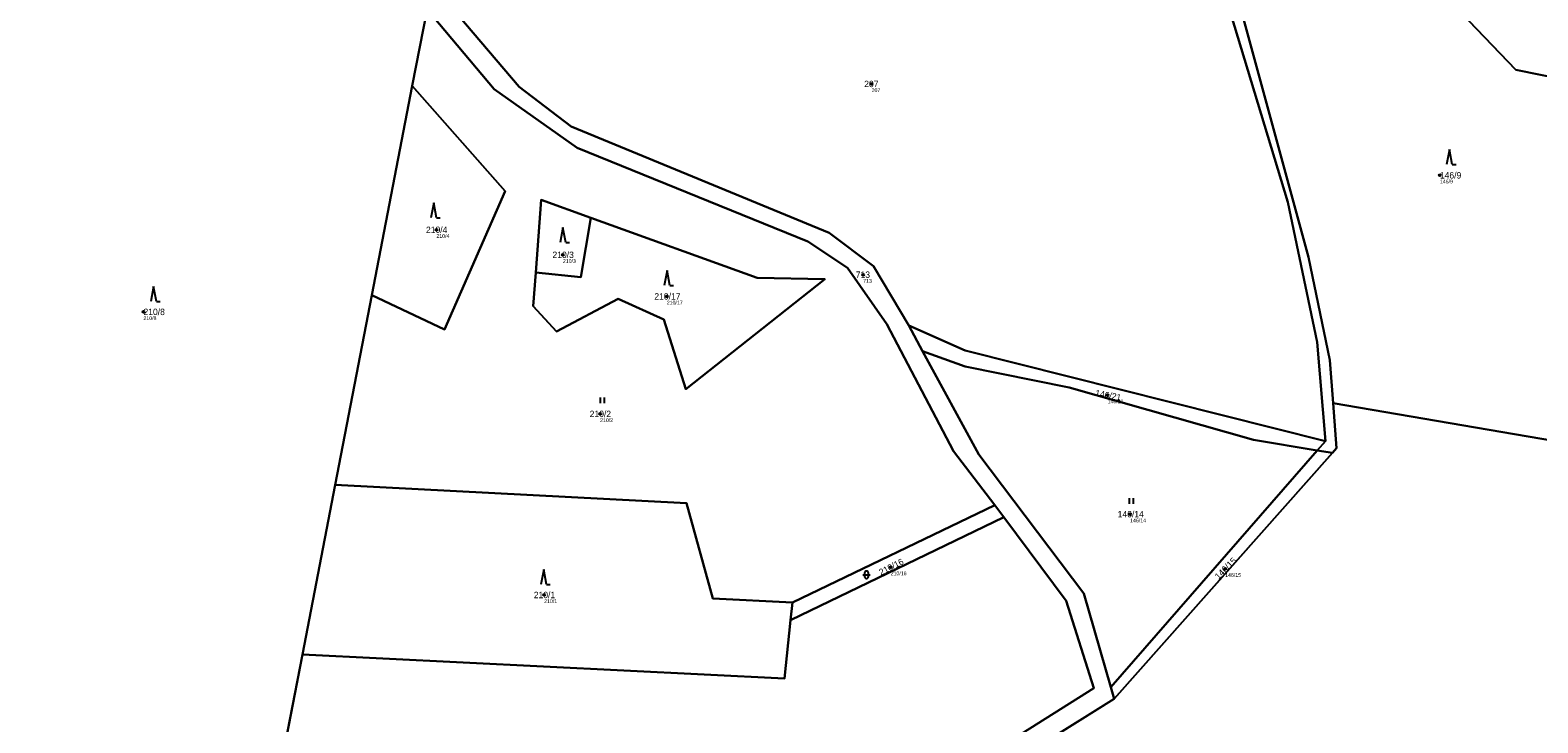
# Model space of a CAD drawing. Extents: x -767985 to -763816, y -1059600 to -1057360.
# Drawn here: x -766944 to -766543.5, y -1058891.9 to -1058707.9 of the extents above; entities that cross this region are included whole.
import ezdxf

# ---------------------------------------------------------------- set-up
doc = ezdxf.new("R2010")
doc.units = 0
for name, color, linetype in [('Definiční body', 7, 'Continuous'), ('Hranice parcel', 7, 'Continuous'), ('Parcelní čísla', 7, 'Continuous'), ('Polygon parcely', 7, 'Continuous'), ('Značky kultur', 7, 'Continuous')]:
    doc.layers.add(name, color=color, linetype=linetype)

msp = doc.modelspace()

# ---------------------------------------------------------------- linework, layer by layer
at = {"layer": 'Definiční body'}
for centre in [(-766720.51, -1058722.21994), (-766569.56, -1058746.48994), (-766836.12, -1058760.95994), (-766802.53, -1058767.60994), (-766722.75, -1058772.88994), (-766774.92, -1058778.64994), (-766913.94, -1058782.76994), (-766657.83, -1058804.88994), (-766792.64, -1058809.86994), (-766651.85, -1058836.50994), (-766715.45, -1058850.57994), (-766626.61, -1058851.01994), (-766807.49, -1058857.97994)]:
    msp.add_circle(centre, 0.25, dxfattribs=at)
at = {"layer": 'Hranice parcel'}
for p, q in [((-766838.62, -1058702.42), (-766842.53, -1058722.71)), ((-766842.53, -1058722.71), (-766853.27, -1058778.37)), ((-766853.27, -1058778.37), (-766862.98, -1058828.7)), ((-766706.99, -1058793.19), (-766710.67, -1058786.43)), ((-766597.89, -1058807.06), (-766528.98, -1058818.77)), ((-766599.95, -1058817.08), (-766602.16, -1058819.62)), ((-766656.99, -1058882.48), (-766602.16, -1058819.62)), ((-766656.1, -1058885.58), (-766598.12, -1058820.24)), ((-766598.12, -1058820.24), (-766602.16, -1058819.62)), ((-766862.98, -1058828.7), (-766871.68, -1058873.81)), ((-766741.53, -1058860.02), (-766687.74, -1058834.16)), ((-766685.37, -1058837.27), (-766687.74, -1058834.16)), ((-766685.37, -1058837.27), (-766742.02, -1058864.65)), ((-766742.02, -1058864.65), (-766741.53, -1058860.02)), ((-766880.48, -1058919.11), (-766871.68, -1058873.81)), ((-766656.99, -1058882.48), (-766656.1, -1058885.58)), ((-766711.95, -1058920.49), (-766656.1, -1058885.58))]:
    msp.add_line(p, q, dxfattribs=at)
for points in [[(-766620.1, -1058632.62), (-766622.28, -1058702.97), (-766604.44, -1058768.25), (-766598.75, -1058795.61), (-766597.89, -1058807.06)], [(-766528.98, -1058818.77), (-766521.82, -1058724.01), (-766549.35, -1058718.51), (-766561.89, -1058705.49), (-766566.65, -1058678.11), (-766585.26, -1058673.13), (-766585.25, -1058653.94), (-766620.1, -1058632.62)], [(-766710.67, -1058786.43), (-766720.03, -1058770.59), (-766731.8, -1058761.8), (-766800.31, -1058733.54), (-766814.1, -1058722.96), (-766844.17, -1058687.65), (-766866.37, -1058655.57), (-766867.09, -1058648.2), (-766865.78, -1058640.13)], [(-766687.74, -1058834.16), (-766698.75, -1058819.75), (-766716.48, -1058786.03), (-766726.88, -1058771.09), (-766737.48, -1058764.06), (-766798.76, -1058739.19), (-766820.82, -1058723.59), (-766838.62, -1058702.42)], [(-766624.96, -1058703.91), (-766609.95, -1058753.6), (-766602.2, -1058790.84), (-766599.95, -1058817.08)], [(-766842.53, -1058722.71), (-766817.89, -1058750.71), (-766833.96, -1058787.48), (-766853.27, -1058778.37)], [(-766809.73, -1058772.31), (-766808.32, -1058753.03), (-766795.09, -1058757.79)], [(-766795.09, -1058757.79), (-766750.94, -1058773.69), (-766732.97, -1058774.1), (-766769.9, -1058803.3), (-766775.67, -1058784.82), (-766787.87, -1058779.3), (-766804.2, -1058787.96), (-766810.38, -1058781.28), (-766809.73, -1058772.31)], [(-766809.73, -1058772.31), (-766797.79, -1058773.59), (-766795.09, -1058757.79)], [(-766599.95, -1058817.08), (-766695.68, -1058793), (-766710.67, -1058786.43)], [(-766602.16, -1058819.62), (-766619.1, -1058816.74), (-766668, -1058802.82), (-766695.63, -1058797.25), (-766706.99, -1058793.19)], [(-766706.99, -1058793.19), (-766692.03, -1058820.66), (-766664.18, -1058857.6), (-766656.99, -1058882.48)], [(-766598.12, -1058820.24), (-766596.99, -1058818.96), (-766597.89, -1058807.06)], [(-766741.53, -1058860.02), (-766762.72, -1058858.87), (-766769.67, -1058833.62), (-766862.98, -1058828.7)], [(-766725.45, -1058923.02), (-766661.51, -1058882.77), (-766668.84, -1058859.54), (-766685.37, -1058837.27)], [(-766871.68, -1058873.81), (-766743.65, -1058880.17), (-766742.02, -1058864.65)]]:
    msp.add_lwpolyline(points, dxfattribs=at)
at = {"layer": 'Polygon parcely'}
for points in [[(-766918.65, -1058338.64), (-766934.8, -1058412.72), (-766943.53, -1058463.01), (-766939.52, -1058508.7), (-766932.84, -1058530.69), (-766894.19, -1058582.94), (-766882.01, -1058605.71), (-766873.43, -1058630.85), (-766870.28, -1058639.83), (-766871.02, -1058655.7), (-766852.8, -1058684.23), (-766838.62, -1058702.42), (-766820.82, -1058723.59), (-766798.76, -1058739.19), (-766737.48, -1058764.06), (-766726.88, -1058771.09), (-766716.48, -1058786.03), (-766698.75, -1058819.75), (-766687.74, -1058834.16), (-766685.37, -1058837.27), (-766668.84, -1058859.54), (-766661.51, -1058882.77), (-766725.45, -1058923.02)], [(-766711.95, -1058920.49), (-766656.1, -1058885.58), (-766656.99, -1058882.48), (-766664.18, -1058857.6), (-766692.03, -1058820.66), (-766706.99, -1058793.19), (-766710.67, -1058786.43), (-766720.03, -1058770.59), (-766731.8, -1058761.8), (-766800.31, -1058733.54), (-766814.1, -1058722.96), (-766844.17, -1058687.65), (-766866.37, -1058655.57), (-766867.09, -1058648.2), (-766865.78, -1058640.13), (-766877.78, -1058608.43), (-766889.77, -1058583.6), (-766928.72, -1058529.92), (-766935.37, -1058507.12), (-766937.51, -1058462.22), (-766929.67, -1058416.96), (-766919.34, -1058374.55), (-766910.78, -1058339.43)], [(-766542.15, -1058462.81), (-766563.63, -1058481.69), (-766620.28, -1058545.98), (-766620.67, -1058559.16), (-766621.04, -1058571.6), (-766622.83, -1058632.06), (-766623.85, -1058666.49), (-766624.96, -1058703.91), (-766609.95, -1058753.6), (-766602.2, -1058790.84), (-766599.95, -1058817.08), (-766602.16, -1058819.62), (-766598.12, -1058820.24), (-766596.99, -1058818.96), (-766597.89, -1058807.06), (-766598.75, -1058795.61), (-766604.44, -1058768.25), (-766622.28, -1058702.97), (-766620.1, -1058632.62), (-766618.6, -1058584.47), (-766617.45, -1058547.45), (-766561.16, -1058484.58), (-766538.98, -1058464.84)]]:
    msp.add_lwpolyline(points, dxfattribs=at)
for points in [[(-766620.1, -1058632.62), (-766585.25, -1058653.94), (-766585.26, -1058673.13), (-766566.65, -1058678.11), (-766561.89, -1058705.49), (-766549.35, -1058718.51), (-766521.82, -1058724.01), (-766528.98, -1058818.77), (-766383.18, -1058843.53), (-766362.61, -1058728.92), (-766342.28, -1058615.61), (-766503.3, -1058597.54), (-766618.6, -1058584.47)], [(-766882.92, -1058642.43), (-766944.55, -1058632.61), (-766972.04, -1058784.16), (-766999.75, -1058936.9), (-766978.13, -1058933.5), (-766968.77, -1058923.73), (-766880.48, -1058919.11), (-766871.68, -1058873.81), (-766862.98, -1058828.7), (-766853.27, -1058778.37), (-766842.53, -1058722.71), (-766838.62, -1058702.42), (-766852.8, -1058684.23), (-766871.02, -1058655.7), (-766870.28, -1058639.83)], [(-766604.44, -1058768.25), (-766598.75, -1058795.61), (-766597.89, -1058807.06), (-766528.98, -1058818.77), (-766521.82, -1058724.01), (-766549.35, -1058718.51), (-766561.89, -1058705.49), (-766566.65, -1058678.11), (-766585.26, -1058673.13), (-766585.25, -1058653.94), (-766620.1, -1058632.62), (-766622.28, -1058702.97)], [(-766599.95, -1058817.08), (-766602.2, -1058790.84), (-766609.95, -1058753.6), (-766624.96, -1058703.91), (-766702.67, -1058686.14), (-766764.67, -1058663.7), (-766806.88, -1058651.91), (-766861.4, -1058640.97), (-766865.78, -1058640.13), (-766867.09, -1058648.2), (-766866.37, -1058655.57), (-766844.17, -1058687.65), (-766814.1, -1058722.96), (-766800.31, -1058733.54), (-766731.8, -1058761.8), (-766720.03, -1058770.59), (-766710.67, -1058786.43), (-766695.68, -1058793)], [(-766853.27, -1058778.37), (-766862.98, -1058828.7), (-766769.67, -1058833.62), (-766762.72, -1058858.87), (-766741.53, -1058860.02), (-766687.74, -1058834.16), (-766698.75, -1058819.75), (-766716.48, -1058786.03), (-766726.88, -1058771.09), (-766737.48, -1058764.06), (-766798.76, -1058739.19), (-766820.82, -1058723.59), (-766838.62, -1058702.42), (-766842.53, -1058722.71), (-766817.89, -1058750.71), (-766833.96, -1058787.48)], [(-766842.53, -1058722.71), (-766853.27, -1058778.37), (-766833.96, -1058787.48), (-766817.89, -1058750.71)], [(-766808.32, -1058753.03), (-766795.09, -1058757.79), (-766750.94, -1058773.69), (-766732.97, -1058774.1), (-766769.9, -1058803.3), (-766775.67, -1058784.82), (-766787.87, -1058779.3), (-766804.2, -1058787.96), (-766810.38, -1058781.28), (-766809.73, -1058772.31)], [(-766795.09, -1058757.79), (-766808.32, -1058753.03), (-766809.73, -1058772.31), (-766797.79, -1058773.59)], [(-766809.73, -1058772.31), (-766810.38, -1058781.28), (-766804.2, -1058787.96), (-766787.87, -1058779.3), (-766775.67, -1058784.82), (-766769.9, -1058803.3), (-766732.97, -1058774.1), (-766750.94, -1058773.69), (-766795.09, -1058757.79), (-766797.79, -1058773.59)], [(-766710.67, -1058786.43), (-766706.99, -1058793.19), (-766695.63, -1058797.25), (-766668, -1058802.82), (-766619.1, -1058816.74), (-766602.16, -1058819.62), (-766599.95, -1058817.08), (-766695.68, -1058793)], [(-766664.18, -1058857.6), (-766656.99, -1058882.48), (-766602.16, -1058819.62), (-766619.1, -1058816.74), (-766668, -1058802.82), (-766695.63, -1058797.25), (-766706.99, -1058793.19), (-766692.03, -1058820.66)], [(-766642.66, -1059107.96), (-766609.43, -1059113.69), (-766580.44, -1059110.55), (-766567.89, -1059152.89), (-766547.74, -1059035.74), (-766527.78, -1058919.74), (-766467.3, -1058954.08), (-766436.78, -1058903.8), (-766484.92, -1058865.4), (-766530.21, -1058835.1), (-766528.98, -1058818.77), (-766597.89, -1058807.06), (-766596.99, -1058818.96), (-766598.12, -1058820.24), (-766656.1, -1058885.58), (-766711.95, -1058920.49), (-766678.98, -1058914.98), (-766654.29, -1058925.95), (-766674.06, -1058985.88), (-766687.94, -1059029.34), (-766700.65, -1059082.39), (-766702.39, -1059098.48)], [(-766656.1, -1058885.58), (-766598.12, -1058820.24), (-766602.16, -1058819.62), (-766656.99, -1058882.48)], [(-766741.53, -1058860.02), (-766762.72, -1058858.87), (-766769.67, -1058833.62), (-766862.98, -1058828.7), (-766871.68, -1058873.81), (-766743.65, -1058880.17), (-766742.02, -1058864.65)], [(-766687.74, -1058834.16), (-766741.53, -1058860.02), (-766742.02, -1058864.65), (-766685.37, -1058837.27)], [(-766757.34, -1058929.45), (-766725.45, -1058923.02), (-766661.51, -1058882.77), (-766668.84, -1058859.54), (-766685.37, -1058837.27), (-766742.02, -1058864.65), (-766743.65, -1058880.17), (-766871.68, -1058873.81), (-766880.48, -1058919.11), (-766834.46, -1058914.47), (-766788.42, -1058937.29)]]:
    msp.add_lwpolyline(points, close=True, dxfattribs=at)
at = {"layer": 'Značky kultur'}
for p, q in [((-766567.02, -1058739.62), (-766567.77, -1058743.62)), ((-766566.27, -1058743.62), (-766567.02, -1058739.62)), ((-766566.27, -1058743.62), (-766565.274, -1058743.62)), ((-766836.85, -1058753.8), (-766837.6, -1058757.8)), ((-766836.1, -1058757.8), (-766836.85, -1058753.8)), ((-766836.1, -1058757.8), (-766835.104, -1058757.8)), ((-766802.53, -1058760.33), (-766803.28, -1058764.33)), ((-766801.78, -1058764.33), (-766802.53, -1058760.33)), ((-766801.78, -1058764.33), (-766800.784, -1058764.33)), ((-766774.85, -1058771.75), (-766775.6, -1058775.75)), ((-766774.1, -1058775.75), (-766774.85, -1058771.75)), ((-766911.23, -1058775.99), (-766911.98, -1058779.99)), ((-766910.48, -1058779.99), (-766911.23, -1058775.99)), ((-766774.1, -1058775.75), (-766773.104, -1058775.75)), ((-766910.48, -1058779.99), (-766909.484, -1058779.99)), ((-766792.491, -1058807.05), (-766792.491, -1058805.55)), ((-766791.49, -1058807.05), (-766791.49, -1058805.55)), ((-766651.971, -1058833.76), (-766651.971, -1058832.26)), ((-766650.97, -1058833.76), (-766650.97, -1058832.26)), ((-766807.62, -1058851.22), (-766808.37, -1058855.22)), ((-766806.87, -1058855.22), (-766807.62, -1058851.22)), ((-766722.861, -1058852.611), (-766720.859, -1058852.611)), ((-766722.361, -1058852.111), (-766722.361, -1058853.112)), ((-766721.359, -1058853.112), (-766721.359, -1058852.111)), ((-766806.87, -1058855.22), (-766805.874, -1058855.22))]:
    msp.add_line(p, q, dxfattribs=at)
for centre, start, end in [((-766721.86, -1058852.1109), 0, 180), ((-766721.86, -1058853.1109), 180, 359.9878861)]:
    msp.add_arc(centre, 0.5, start, end, dxfattribs=at)

# ---------------------------------------------------------------- texts
at = {"layer": 'Definiční body'}
for s, p in [('207', (-766720.51, -1058724.376)), ('146/9', (-766569.56, -1058748.646)), ('210/4', (-766836.12, -1058763.116)), ('210/3', (-766802.53, -1058769.766)), ('713', (-766722.75, -1058775.046)), ('210/17', (-766774.92, -1058780.806)), ('210/8', (-766913.94, -1058784.926)), ('146/21', (-766657.83, -1058807.046)), ('210/2', (-766792.64, -1058812.026)), ('146/14', (-766651.85, -1058838.666)), ('210/16', (-766715.45, -1058852.736)), ('146/15', (-766626.61, -1058853.176)), ('210/1', (-766807.49, -1058860.136))]:
    msp.add_text(s, height=0.999996, dxfattribs=at).set_placement(p)
at = {"layer": 'Parcelní čísla'}
for s, p in [('207', (-766722.484, -1058723.07)), ('146/9', (-766569.56, -1058747.34)), ('210/4', (-766838.893, -1058761.81)), ('210/3', (-766805.303, -1058768.46)), ('713', (-766724.724, -1058773.74)), ('210/17', (-766778.225, -1058779.5)), ('210/8', (-766913.94, -1058783.62)), ('210/2', (-766795.413, -1058810.72)), ('146/14', (-766655.155, -1058837.36)), ('210/1', (-766810.263, -1058858.83))]:
    msp.add_text(s, height=1.699998, dxfattribs=at).set_placement(p)
for s, rotation, p in [('146/21', 349, (-766661.237, -1058805.093)), ('210/16', 27, (-766718.009, -1058852.838)), ('146/15', 45, (-766628.346, -1058853.958))]:
    msp.add_text(s, height=1.699998, rotation=rotation, dxfattribs=at).set_placement(p)

doc.saveas('drawing.dxf')
